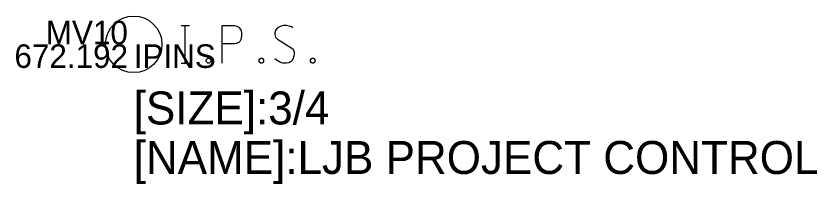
# Model space of a CAD drawing. Extents: x 1660019 to 1662995, y 619975 to 620342.
# Drawn here: x 1662960.59 to 1662994.66, y 620181.86 to 620188.98 of the extents above; entities that cross this region are included whole.
import ezdxf

# ---------------------------------------------------------------- set-up
doc = ezdxf.new("R2010")
doc.units = 0
for name, color, linetype in [('BR_X_Rail_Object', 7, 'Continuous'), ('RD_X_GR_Bar', 7, 'Continuous'), ('RD_X_Wall', 7, 'Continuous'), ('SV_P_Mon_Cells_Set_Text', 7, 'Continuous'), ('SV_X_Break_Lines', 7, 'Continuous')]:
    doc.layers.add(name, color=color, linetype=linetype)

msp = doc.modelspace()

# ---------------------------------------------------------------- linework, layer by layer
at = {"layer": 'SV_X_Break_Lines'}
for points in [[(1662967.619, 620188.586), (1662967.972, 620188.586)], [(1662967.795, 620186.986), (1662967.795, 620188.586)], [(1662969.361, 620186.986), (1662969.361, 620188.586), (1662969.89, 620188.586), (1662969.945, 620188.573), (1662970.022, 620188.548), (1662970.055, 620188.523), (1662970.088, 620188.497), (1662970.132, 620188.434), (1662970.165, 620188.371), (1662970.187, 620188.271), (1662970.187, 620188.119), (1662970.176, 620188.069), (1662970.154, 620187.993), (1662970.11, 620187.905), (1662970.066, 620187.868), (1662970.033, 620187.842), (1662969.978, 620187.817), (1662969.89, 620187.805), (1662969.361, 620187.805)], [(1662972.37, 620188.472), (1662972.348, 620188.497), (1662972.315, 620188.523), (1662972.216, 620188.56), (1662972.094, 620188.586), (1662972.006, 620188.586), (1662971.973, 620188.586), (1662971.83, 620188.548), (1662971.709, 620188.472), (1662971.631, 620188.371), (1662971.609, 620188.271), (1662971.609, 620188.195), (1662971.631, 620188.094), (1662971.72, 620188.006), (1662972.326, 620187.628), (1662972.381, 620187.578), (1662972.403, 620187.527), (1662972.425, 620187.452), (1662972.425, 620187.376), (1662972.414, 620187.301), (1662972.403, 620187.25), (1662972.381, 620187.187), (1662972.359, 620187.137), (1662972.337, 620187.099), (1662972.304, 620187.061), (1662972.271, 620187.036), (1662972.227, 620187.011), (1662972.194, 620186.998), (1662972.094, 620186.986), (1662971.94, 620186.986), (1662971.841, 620187.011), (1662971.697, 620187.099), (1662971.609, 620187.175)], [(1662968.754, 620187.2), (1662968.809, 620187.2), (1662968.843, 620187.175), (1662968.876, 620187.124), (1662968.876, 620187.061), (1662968.843, 620187.011), (1662968.809, 620186.986), (1662968.754, 620186.986), (1662968.721, 620187.011), (1662968.688, 620187.061), (1662968.688, 620187.124), (1662968.721, 620187.175), (1662968.754, 620187.2)], [(1662971.003, 620187.2), (1662971.058, 620187.2), (1662971.091, 620187.175), (1662971.124, 620187.124), (1662971.124, 620187.061), (1662971.091, 620187.011), (1662971.058, 620186.986), (1662971.003, 620186.986), (1662970.97, 620187.011), (1662970.937, 620187.061), (1662970.937, 620187.124), (1662970.97, 620187.175), (1662971.003, 620187.2)], [(1662973.186, 620187.2), (1662973.241, 620187.2), (1662973.274, 620187.175), (1662973.307, 620187.124), (1662973.307, 620187.061), (1662973.274, 620187.011), (1662973.241, 620186.986), (1662973.186, 620186.986), (1662973.152, 620187.011), (1662973.12, 620187.061), (1662973.12, 620187.124), (1662973.152, 620187.175), (1662973.186, 620187.2)], [(1662967.619, 620186.986), (1662967.972, 620186.986)]]:
    msp.add_lwpolyline(points, dxfattribs=at)
msp.add_circle((1662965.6, 620187.784), 1.2, dxfattribs=at)

# ---------------------------------------------------------------- texts
at = {"layer": 'BR_X_Rail_Object'}
msp.add_text('IPINS', height=1, dxfattribs=at).set_placement((1662965.6, 620186.784))
at = {"layer": 'RD_X_GR_Bar'}
msp.add_text('672.192', height=1, dxfattribs=at).set_placement((1662960.527, 620186.784))
at = {"layer": 'RD_X_Wall'}
msp.add_text('MV10', height=1, dxfattribs=at).set_placement((1662961.86, 620187.784))
at = {"layer": 'SV_P_Mon_Cells_Set_Text'}
for s, p in [('[SIZE]:3/4', (1662965.6, 620184.384)), ('[NAME]:LJB PROJECT CONTROL', (1662965.6, 620182.284))]:
    msp.add_text(s, height=1.4, dxfattribs=at).set_placement(p)

doc.saveas('drawing.dxf')
